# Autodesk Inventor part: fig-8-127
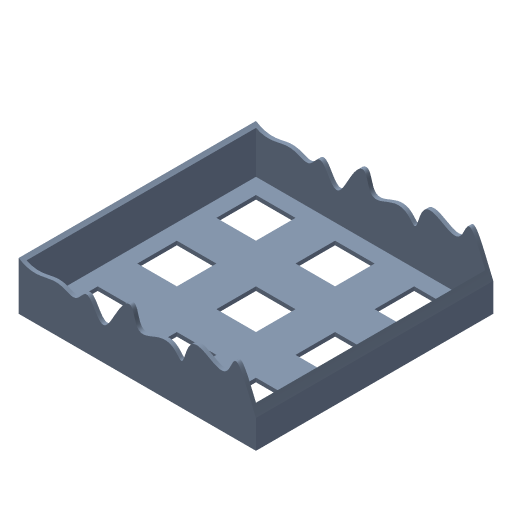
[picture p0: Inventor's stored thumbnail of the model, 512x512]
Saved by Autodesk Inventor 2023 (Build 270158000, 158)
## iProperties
Part Number: fig-8-127
Document SubType Name: Modeling
Created: 2002-12
Designer: deepak
Density: 1 g/cm^3
Material: Generic
Appearance: Light Steel Blue
Control State: 0
Master: False
Checked Out: False
Shininess: 64.0
Length Units: 11269
Angle Units: 11279
Time Units: 11290
Mass Units: 11283
Length Display Precision: 3
Angle Display Precision: 2
Compacted: True
Density: 0.0
Volumn: 0.0
Area: 0.0
PropertySet Name: Model Information
Author: deepak
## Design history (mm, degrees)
sketch "Sketch1"
  geometry: L1 (-32.188, 30.089)-(27.812, 30.089); L2 (27.812, 30.089)-(27.812, -29.911); L3 (27.812, -29.911)-(-32.188, -29.911); L4 (-32.188, -29.911)-(-32.188, 30.089)
  constraints: 8 end point, 2 parallel, 1 horizontal, 1 perpendicular
  dimensions: "d0" = 60 distance of L1.start L1.end; "d1" = 60 distance of L3.end L1.start
extrude "Extrusion1" new body sketch "Sketch1" stored distance "d2" = 20; taper "d3" = 0 deg
shell "Shell2" dims "d21" = 1
sketch "Sketch5"
  geometry: L1 (-27.812, 30.089)-(32.188, 30.089) reference; L2 (-27.812, -29.911)-(-27.812, 30.089) reference; L3 (-22.812, 25.089)-(-12.812, 25.089); L4 (-12.812, 25.089)-(-12.812, 15.089); L5 (-12.812, 15.089)-(-22.812, 15.089); L6 (-22.812, 15.089)-(-22.812, 25.089)
  constraints: 8 end point, 2 parallel, 1 horizontal, 1 perpendicular
  dimensions: "d8" = 10 distance of L3.start L3.end; "d9" = 10 distance of L5.end L3.start; "d10" = 5 distance between parallel lines of L2 L6; "d11" = 5 distance between parallel lines of L1 L3
extrude "Extrusion2" cut sketch "Sketch5" distance "d12" = 50; taper "d13" = 0 deg
pattern_linear "Rectangular Pattern1" dims "d16" = 20, "d19" = 20
sketch "Sketch2"
  geometry: 17 further points
  constraints: 17 other
extrude_surface "ExtrusionSrf1" sketch "Sketch2" dims "d4" = 70, "d5" = 0
split "Split2"
body "Solid1"
body "Srf1"
